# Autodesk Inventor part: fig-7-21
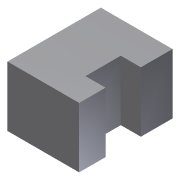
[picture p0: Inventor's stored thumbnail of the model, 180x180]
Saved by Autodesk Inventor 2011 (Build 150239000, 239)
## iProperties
Created: 2010-03
Part Number: fig-7-21
Document SubType Name: Modeling
Designer: CADSoft
Density: 1 g/cm^3
Author: CADSoft
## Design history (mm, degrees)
sketch "Sketch1"
  geometry: L1 (-16.027, 20.205)-(19.726, 20.205); L2 (19.726, 20.205)-(19.726, -26.37); L3 (19.726, -26.37)-(-16.027, -26.37); L4 (-16.027, -26.37)-(-16.027, 20.205); 1 further point
  constraints: 8 end point, 2 parallel, 1 horizontal, 1 perpendicular
extrude "Extrusion1" new body sketch "Sketch1" distance "d0" = 30; taper "d1" = 0 deg
sketch "Sketch2"
  geometry: L1 (-30, 46.575)-(-30, 0) reference; L2 (0, 46.575)-(0, 0) reference; L3 (-30, 13.159)-(0, 13.159); L4 (0, 13.159)-(0, 33.527); L5 (0, 33.527)-(-30, 33.527); L6 (-30, 33.527)-(-30, 13.159); 1 further point
  constraints: 8 end point, 2 parallel, 2 point on line, 1 horizontal, 1 perpendicular
extrude "Extrusion2" cut sketch "Sketch2" distance "d2" = 10; taper "d3" = 0 deg
feature "Move Face1"
body "Solid1"
